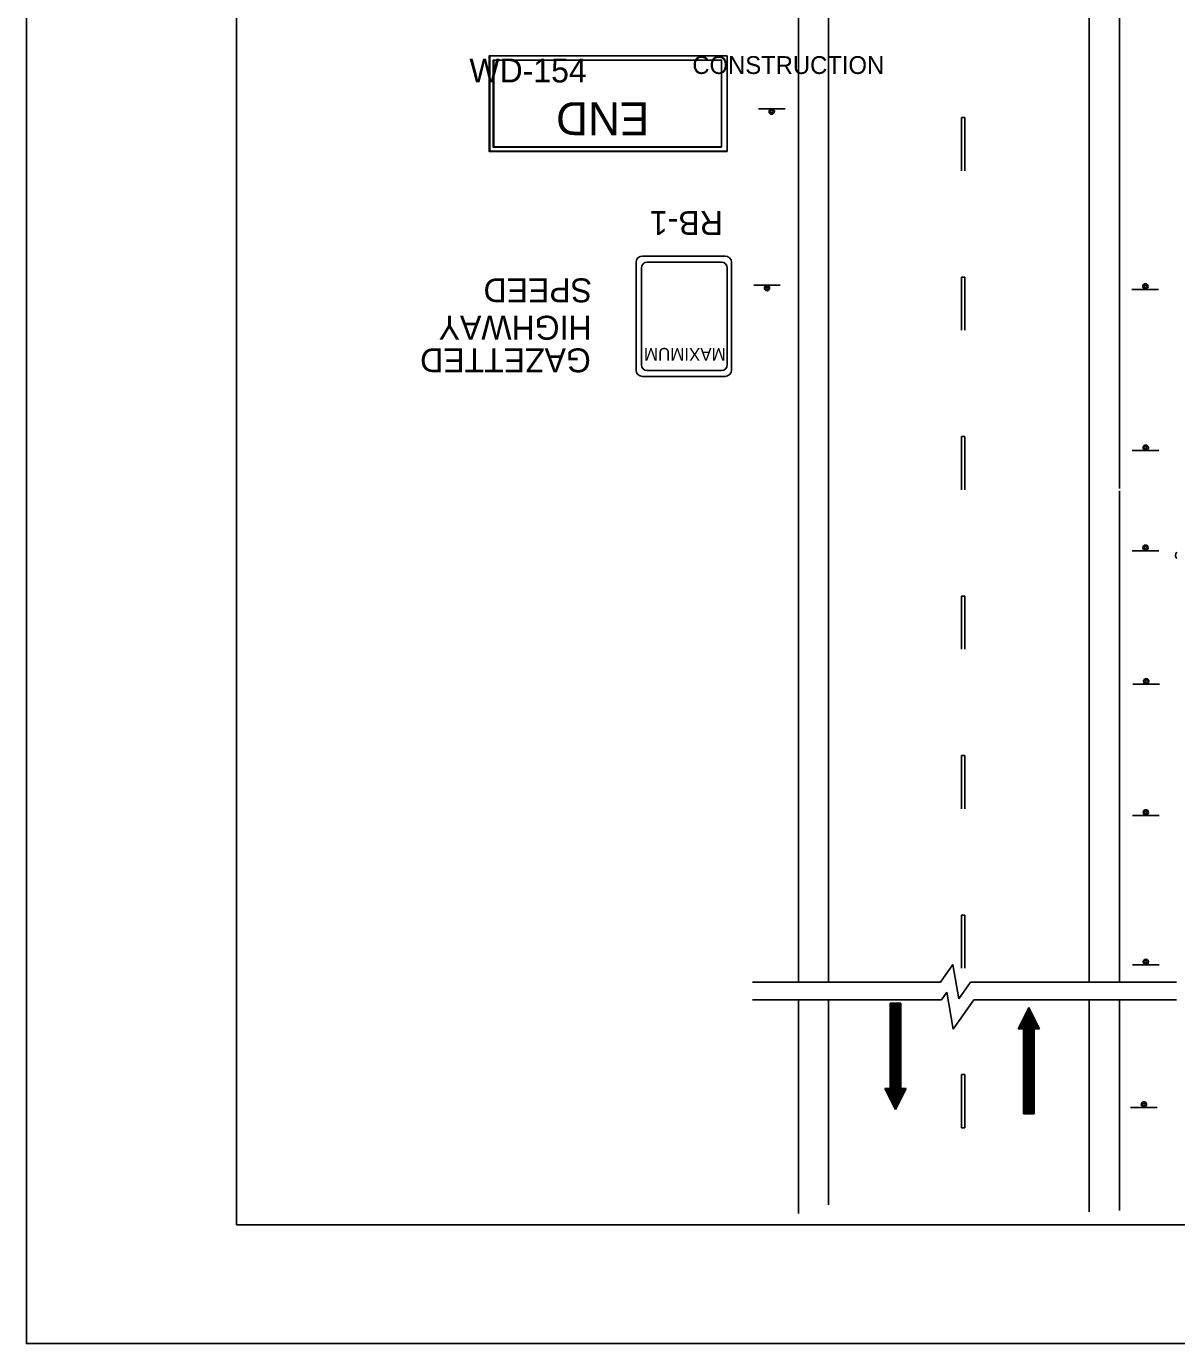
# Model space of a CAD drawing. Extents: x 1372 to 1588, y 125 to 404.
# Drawn here: x 1372.1 to 1476.7, y 125 to 244.9 of the extents above; entities that cross this region are included whole.
import ezdxf

# ---------------------------------------------------------------- set-up
doc = ezdxf.new("R2010")
doc.units = 0
for name, color, linetype in [('Level 10', 7, 'Continuous'), ('Level 2', 7, 'Continuous'), ('Level 44', 7, 'Continuous'), ('Level 60', 7, 'Continuous')]:
    doc.layers.add(name, color=color, linetype=linetype)

msp = doc.modelspace()

# ---------------------------------------------------------------- linework, layer by layer
at = {"layer": 'Level 10'}
for p, q in [((1445.05, 372.63), (1445.05, 157.87)), ((1468.76, 372.63), (1468.76, 157.87)), ((1471.51, 372.63), (1471.51, 202.79)), ((1442.33, 157.87), (1442.33, 334.98)), ((1471.51, 157.87), (1471.51, 202.59)), ((1442.33, 136.83), (1442.33, 156.25)), ((1445.05, 156.25), (1445.05, 137.61)), ((1450.66, 148.21), (1450.66, 155.95)), ((1451.62, 155.95), (1450.66, 155.95)), ((1450.66, 147.25), (1450.66, 155.95)), ((1450.78, 147), (1450.78, 155.95)), ((1450.9, 146.76), (1450.9, 155.95)), ((1451.02, 146.52), (1451.02, 155.95)), ((1451.14, 146.28), (1451.14, 155.95)), ((1451.26, 146.52), (1451.26, 155.95)), ((1451.38, 146.76), (1451.38, 155.95)), ((1451.5, 147), (1451.5, 155.95)), ((1451.62, 148.21), (1451.62, 155.95)), ((1451.62, 147.25), (1451.62, 155.95)), ((1468.76, 156.25), (1468.76, 136.96)), ((1471.51, 137.09), (1471.51, 156.25)), ((1463.27, 155.56), (1462.3, 153.62)), ((1462.91, 154.83), (1462.91, 145.88)), ((1463.03, 155.07), (1463.03, 145.88)), ((1463.15, 155.31), (1463.15, 145.88)), ((1463.27, 155.56), (1463.27, 145.88)), ((1463.27, 155.56), (1464.24, 153.62)), ((1463.39, 155.31), (1463.39, 145.88)), ((1463.51, 155.07), (1463.51, 145.88)), ((1463.63, 154.83), (1463.63, 145.88)), ((1462.3, 153.62), (1462.79, 153.62)), ((1462.42, 153.86), (1462.42, 153.62)), ((1462.54, 154.1), (1462.54, 153.62)), ((1462.66, 154.35), (1462.66, 153.62)), ((1462.79, 154.59), (1462.79, 145.88)), ((1462.79, 153.62), (1462.79, 145.88)), ((1463.75, 154.59), (1463.75, 145.88)), ((1463.75, 153.62), (1463.75, 145.88)), ((1463.75, 153.62), (1464.24, 153.62)), ((1463.87, 154.35), (1463.87, 153.62)), ((1464, 154.1), (1464, 153.62)), ((1464.12, 153.86), (1464.12, 153.62)), ((1451.14, 146.28), (1450.17, 148.21)), ((1450.66, 148.21), (1450.17, 148.21)), ((1450.29, 147.97), (1450.29, 148.21)), ((1450.41, 147.73), (1450.41, 148.21)), ((1450.54, 147.49), (1450.54, 148.21)), ((1451.14, 146.28), (1452.11, 148.21)), ((1452.11, 148.21), (1451.62, 148.21)), ((1451.75, 147.49), (1451.75, 148.21)), ((1451.87, 147.73), (1451.87, 148.21)), ((1451.99, 147.97), (1451.99, 148.21)), ((1462.79, 145.88), (1463.75, 145.88))]:
    msp.add_line(p, q, dxfattribs=at)
at = {"layer": 'Level 2'}
for p, q in [((1457.15, 236.55), (1457.15, 231.71)), ((1457.44, 236.55), (1457.15, 236.55)), ((1457.44, 231.71), (1457.44, 236.55)), ((1457.15, 222.03), (1457.15, 217.2)), ((1457.44, 222.03), (1457.15, 222.03)), ((1457.44, 217.2), (1457.44, 222.03)), ((1457.15, 207.52), (1457.15, 202.68)), ((1457.44, 207.52), (1457.15, 207.52)), ((1457.44, 202.68), (1457.44, 207.52)), ((1457.15, 193.01), (1457.15, 188.17)), ((1457.44, 193.01), (1457.15, 193.01)), ((1457.44, 188.17), (1457.44, 193.01)), ((1457.15, 178.49), (1457.15, 173.65)), ((1457.44, 178.49), (1457.15, 178.49)), ((1457.44, 173.65), (1457.44, 178.49)), ((1457.15, 163.98), (1457.15, 159.14)), ((1457.44, 163.98), (1457.15, 163.98)), ((1457.44, 159.14), (1457.44, 163.98)), ((1457.15, 149.46), (1457.15, 144.63)), ((1457.44, 149.46), (1457.15, 149.46)), ((1457.44, 144.63), (1457.44, 149.46)), ((1457.15, 144.63), (1457.44, 144.63))]:
    msp.add_line(p, q, dxfattribs=at)
for points in [[(1435.82, 233.47), (1414.16, 233.47), (1414.16, 242.17), (1435.82, 242.17)], [(1435.82, 233.5), (1414.22, 233.5), (1414.22, 242.17), (1435.82, 242.17)], [(1435.31, 233.86), (1414.53, 233.86), (1414.53, 241.77), (1435.31, 241.77)], [(1435.31, 233.88), (1414.6, 233.88), (1414.6, 241.78), (1435.31, 241.78)]]:
    msp.add_lwpolyline(points, close=True, dxfattribs=at)
at = {"layer": 'Level 44'}
for p, q in [((1441.1, 237.36), (1438.68, 237.36)), ((1427.54, 213.57), (1427.54, 223.37)), ((1428.12, 223.95), (1435.64, 223.95)), ((1428.54, 223.39), (1435.31, 223.39)), ((1435.5, 223.71), (1435.5, 223.71)), ((1436.22, 223.37), (1436.22, 213.57)), ((1436.22, 223.37), (1436.22, 223.37)), ((1428.02, 214.05), (1428.02, 222.87)), ((1435.83, 222.87), (1435.83, 214.05)), ((1435.83, 222.87), (1435.83, 222.87)), ((1440.66, 221.31), (1438.25, 221.31)), ((1472.66, 220.92), (1475.08, 220.92)), ((1472.66, 220.92), (1475.08, 220.92)), ((1435.31, 213.53), (1428.54, 213.53)), ((1435.64, 212.99), (1428.12, 212.99)), ((1472.69, 206.24), (1475.11, 206.24)), ((1472.68, 197.13), (1475.1, 197.13)), ((1472.74, 184.98), (1475.16, 184.98)), ((1472.7, 173.05), (1475.12, 173.05)), ((1455.23, 157.87), (1456.37, 159.49)), ((1456.37, 159.49), (1456.92, 156.37)), ((1472.7, 159.44), (1475.12, 159.44)), ((1438.14, 157.87), (1455.23, 157.87)), ((1456.92, 156.37), (1457.98, 157.87)), ((1457.98, 157.87), (1476.7, 157.87)), ((1438.14, 156.25), (1455.32, 156.25)), ((1455.32, 156.25), (1455.81, 156.95)), ((1455.81, 156.95), (1456.4, 153.59)), ((1456.4, 153.59), (1458.28, 156.25)), ((1458.28, 156.25), (1476.7, 156.25)), ((1472.54, 146.48), (1474.96, 146.48))]:
    msp.add_line(p, q, dxfattribs=at)
for centre, radius in [((1439.88, 237.09), 0.242), ((1439.88, 237.09), 0.121), ((1439.45, 221.04), 0.242), ((1439.45, 221.04), 0.121), ((1473.88, 221.19), 0.242), ((1473.88, 221.19), 0.242), ((1473.88, 221.19), 0.121), ((1473.88, 221.19), 0.121), ((1473.91, 206.51), 0.242), ((1473.91, 206.51), 0.121), ((1473.89, 197.41), 0.242), ((1473.89, 197.41), 0.121), ((1473.95, 185.25), 0.242), ((1473.95, 185.25), 0.121), ((1473.92, 173.32), 0.242), ((1473.92, 173.32), 0.121), ((1473.92, 159.71), 0.242), ((1473.92, 159.71), 0.121), ((1473.75, 146.75), 0.242), ((1473.75, 146.75), 0.121)]:
    msp.add_circle(centre, radius, dxfattribs=at)
for centre, radius, start, end in [((1428.12, 223.37), 0.58, 90, 180), ((1428.54, 222.87), 0.522, 90, 180), ((1435.31, 222.87), 0.522, 360, 90), ((1435.64, 223.37), 0.58, 360, 90), ((1428.12, 213.57), 0.58, 180, 270), ((1428.54, 214.05), 0.522, 180, 270), ((1435.31, 214.05), 0.522, 270, 360), ((1435.64, 213.57), 0.58, 270, 360), ((1477.05, 196.71), 0.418, 135, 225)]:
    msp.add_arc(centre, radius, start, end, dxfattribs=at)
at = {"layer": 'Level 60'}
for points in [[(1372.06, 403.98), (1588.06, 403.98), (1588.06, 124.98), (1372.06, 124.98)], [(1391.18, 393.17), (1578.06, 393.17), (1578.06, 135.79), (1391.18, 135.79)]]:
    msp.add_lwpolyline(points, close=True, dxfattribs=at)

# ---------------------------------------------------------------- texts
at = {"layer": 'Level 10'}
for s, height, rotation, p in [('WD-154', 2.177, 360, (1412.37, 239.75)), ('RB-1', 2.177, 180, (1435.43, 228.04)), ('SPEED', 2.177, 180, (1423.53, 221.92)), ('HIGHWAY', 2.178, 180, (1423.49, 218.52)), ('GAZETTED', 2.177, 180, (1423.42, 215.55))]:
    msp.add_text(s, height=height, rotation=rotation, dxfattribs=at).set_placement(p)
at = {"layer": 'Level 44'}
for s, height, rotation, p in [('CONSTRUCTION', 1.62, 360, (1432.66, 240.52)), ('END', 3, 180, (1428.74, 237.95)), ('MAXIMUM', 1.15, 180, (1435.69, 215.59))]:
    msp.add_text(s, height=height, rotation=rotation, dxfattribs=at).set_placement(p)

doc.saveas('drawing.dxf')
